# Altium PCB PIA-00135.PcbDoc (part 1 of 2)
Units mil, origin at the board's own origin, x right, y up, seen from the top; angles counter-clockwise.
Board outline 5630 x 2198.54 mil, 6 copper layers (Top Layer, Mid-Layer 1, Mid-Layer 2, Mid-Layer 3, Mid-Layer 4, Bottom Layer), stack 61.94 mil thick; 90 components, 35 nets, 210 pads, 457 vias.
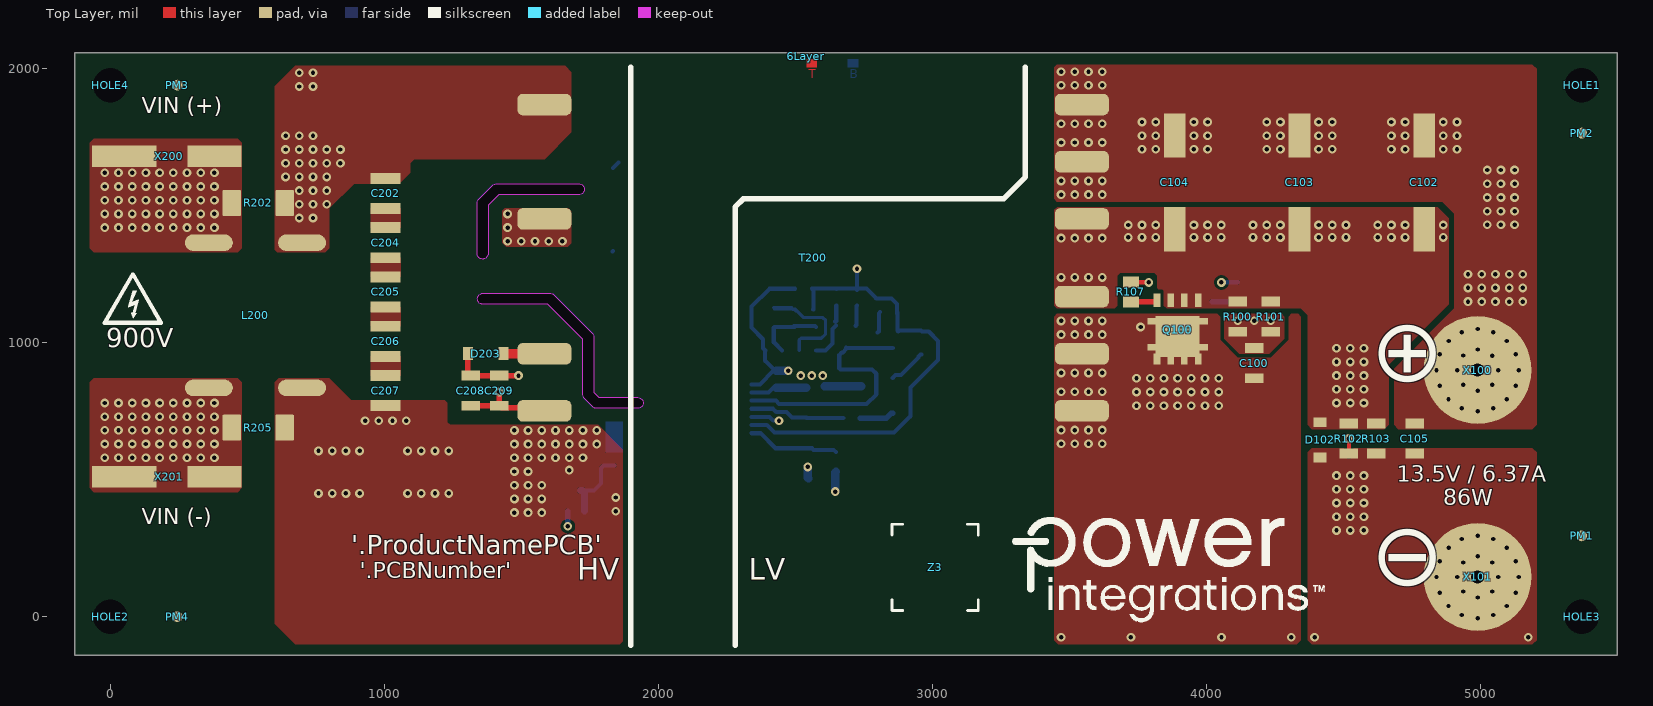
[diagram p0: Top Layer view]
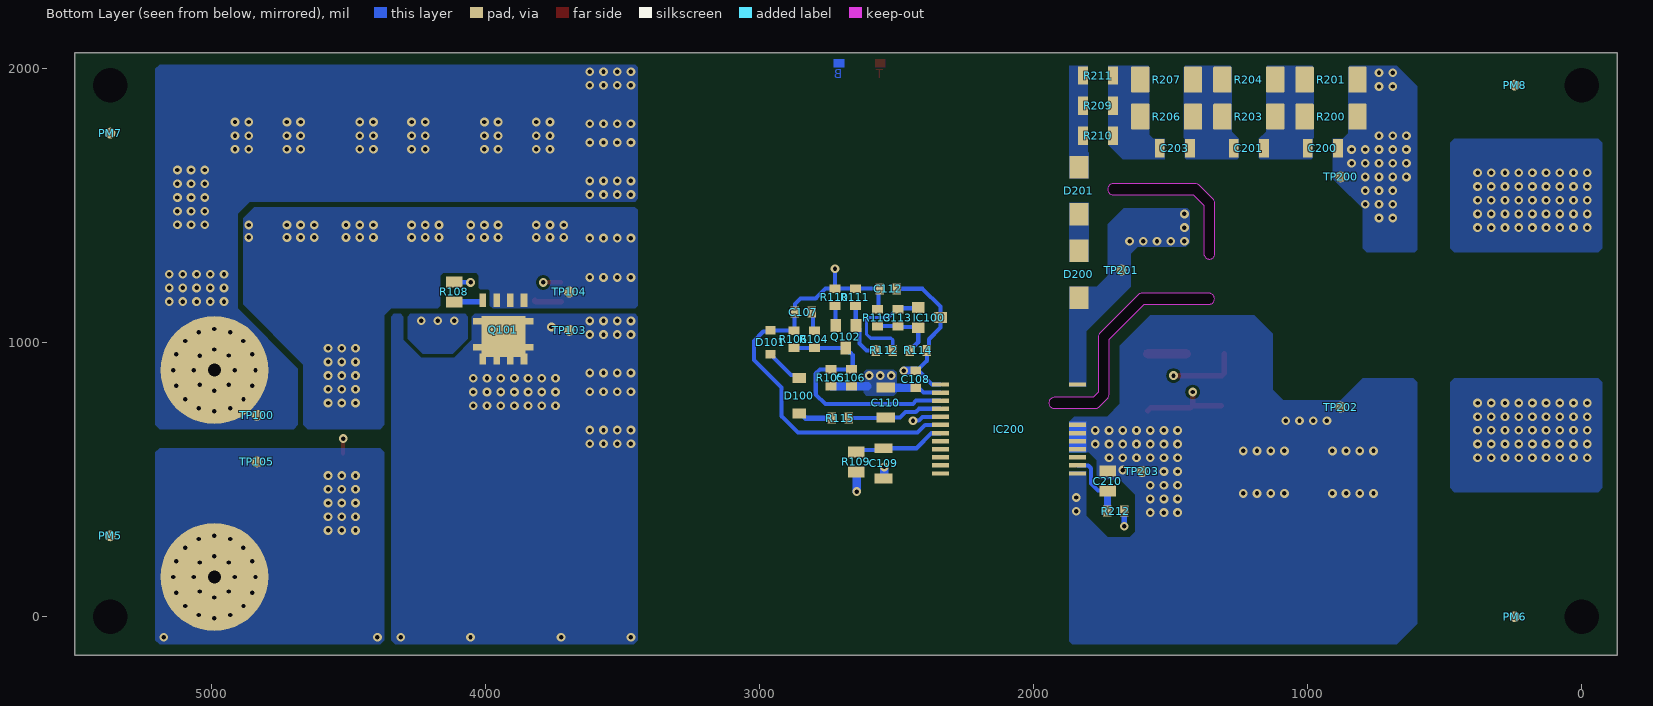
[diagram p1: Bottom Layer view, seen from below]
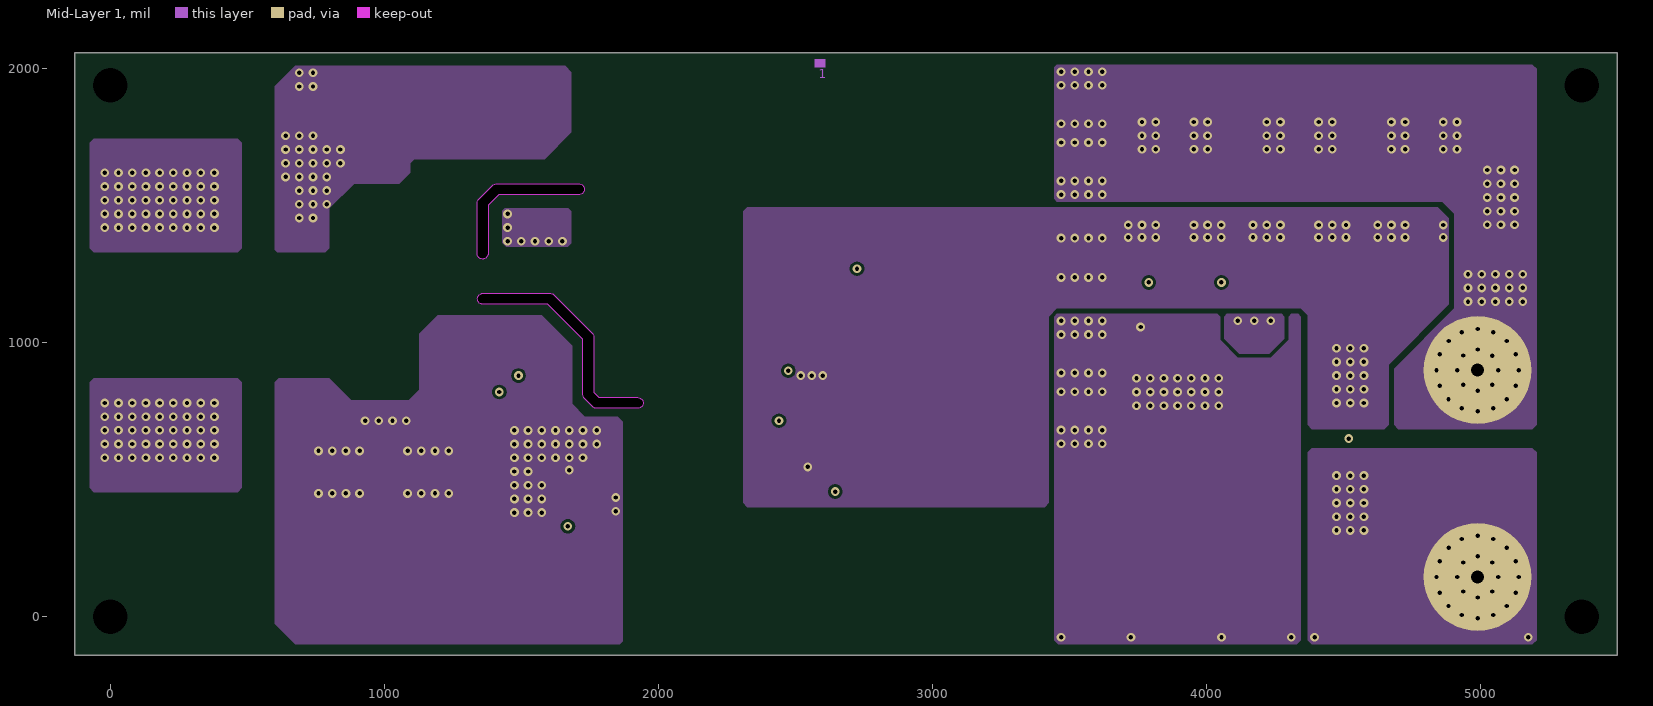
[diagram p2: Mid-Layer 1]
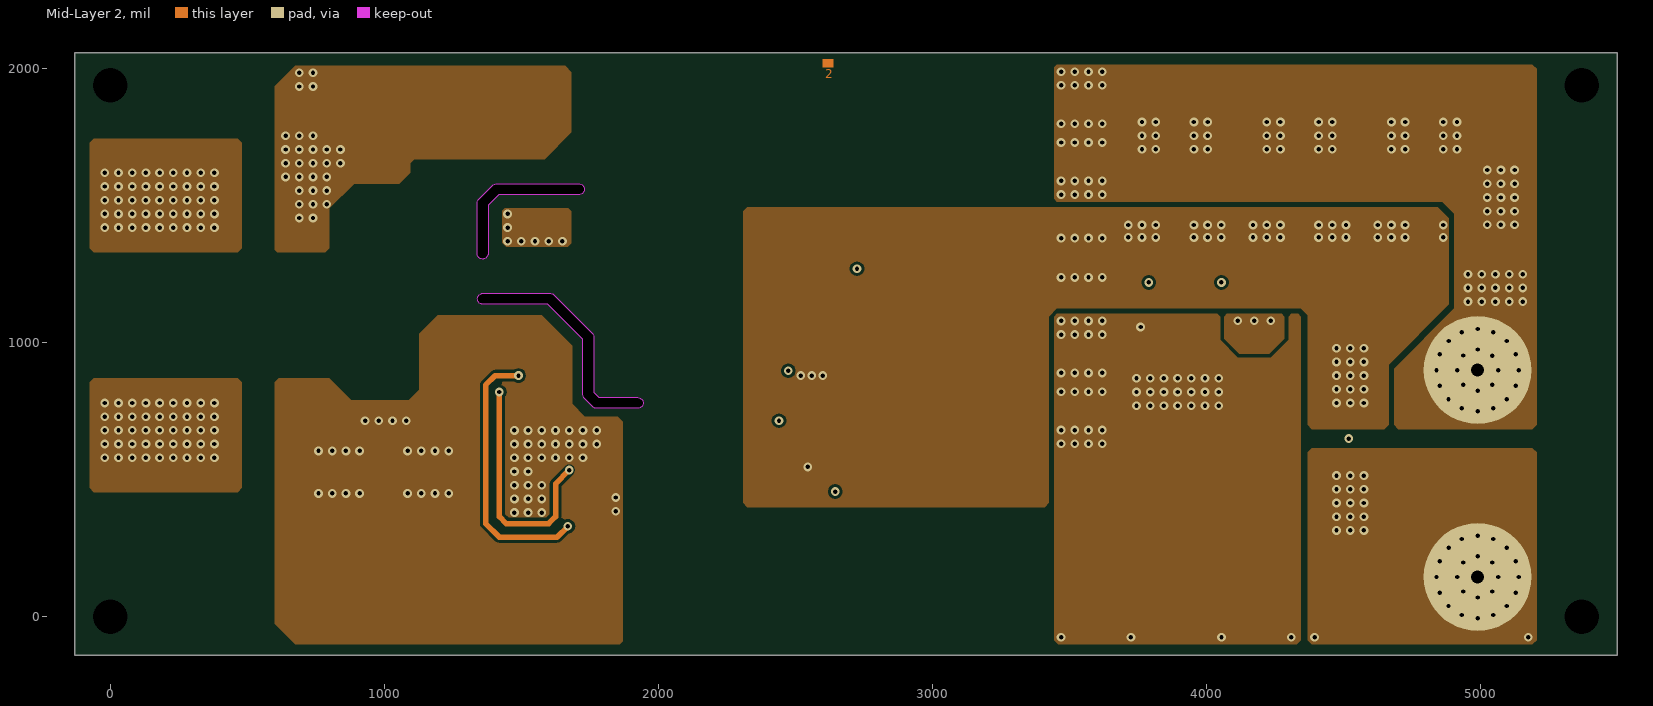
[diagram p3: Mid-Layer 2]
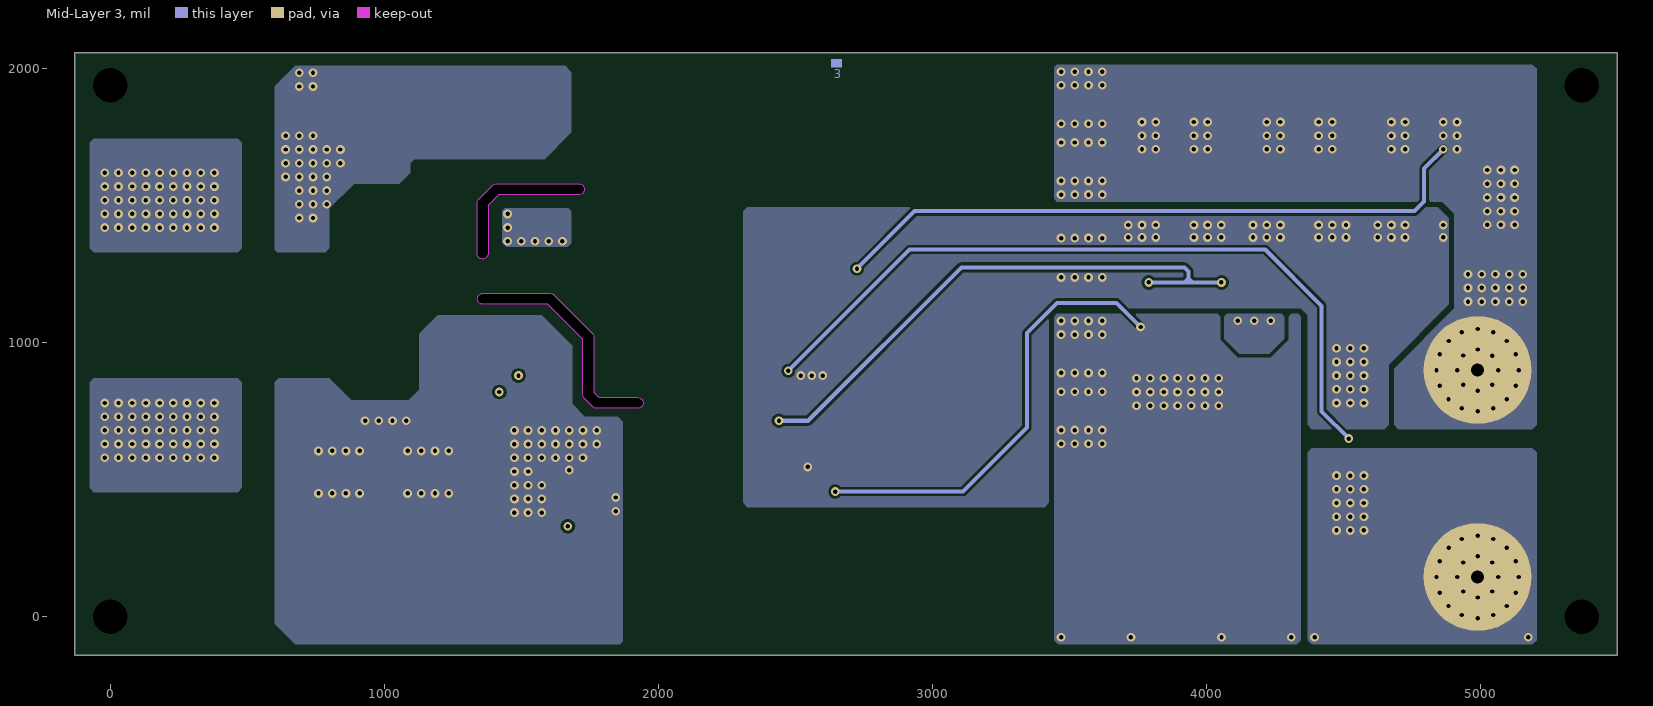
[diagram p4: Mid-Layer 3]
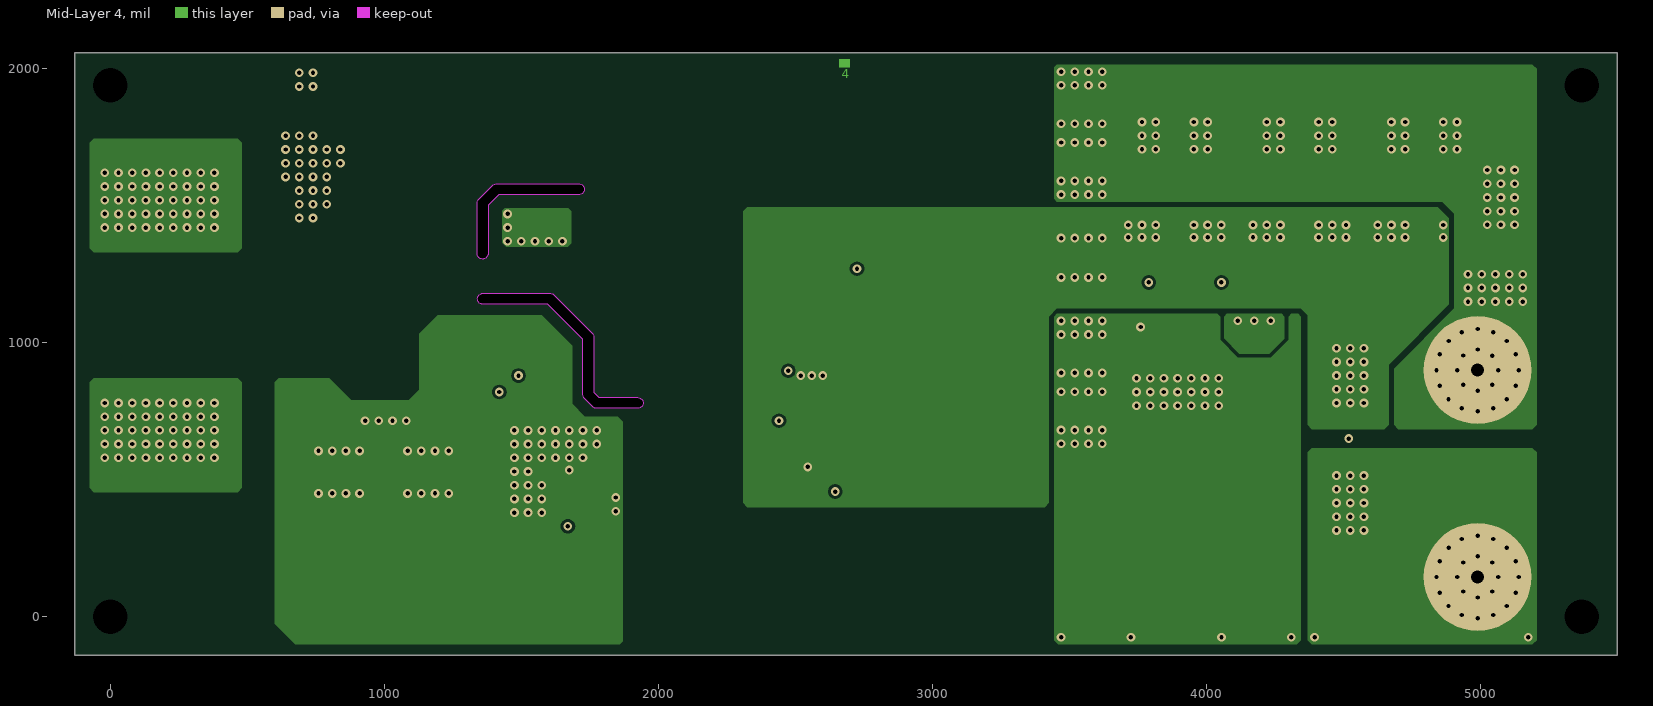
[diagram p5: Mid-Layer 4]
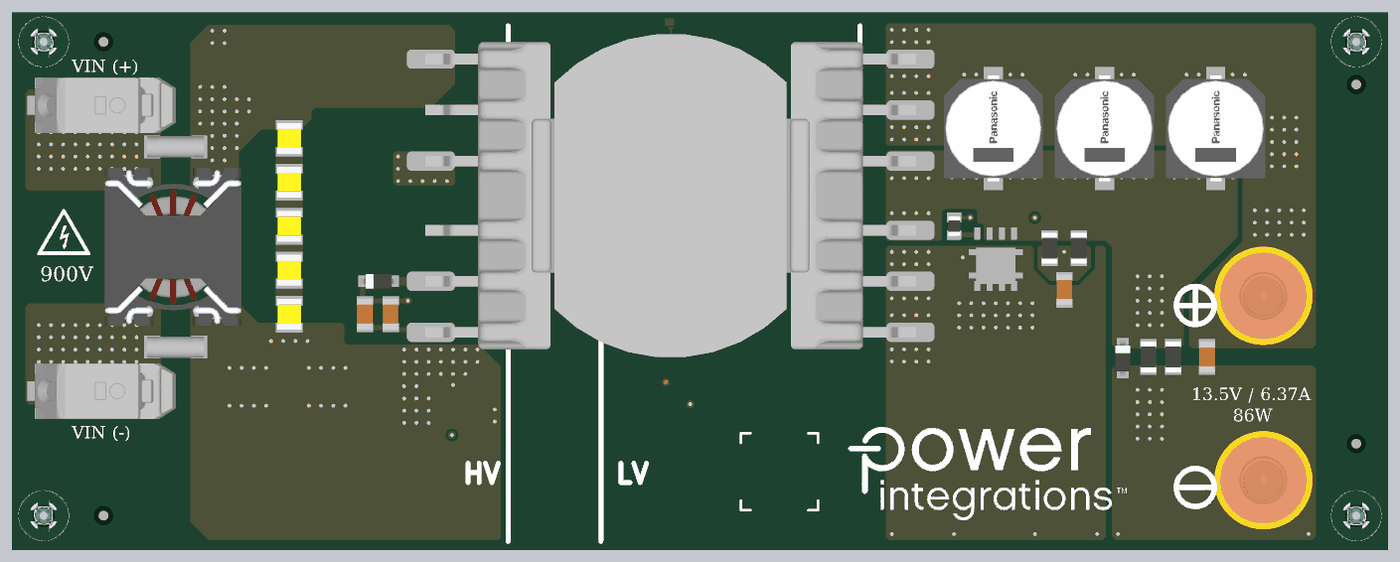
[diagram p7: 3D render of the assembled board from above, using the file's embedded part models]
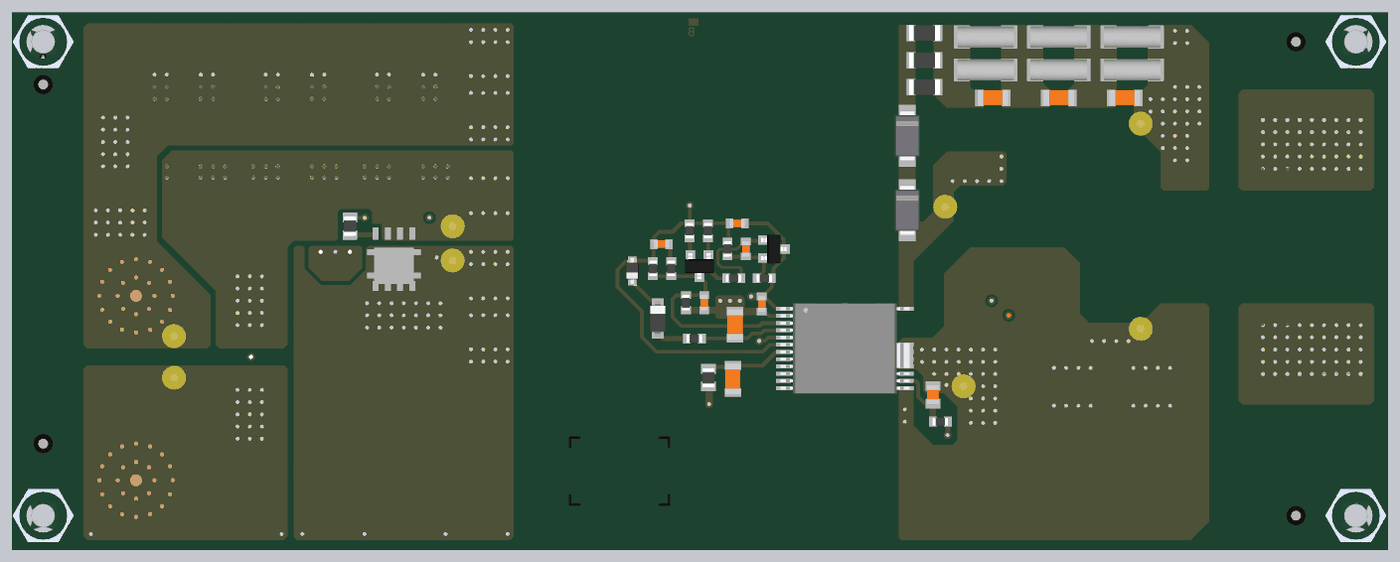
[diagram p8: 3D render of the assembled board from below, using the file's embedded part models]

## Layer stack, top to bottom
Top Solder: solder mask 0.39, Solder Resist, Dk 3.5
Top Layer: signal copper 1.4
Dielectric 8: prepreg 4.72, PP-1080, Dk 3.9
Mid-Layer 1: signal copper 1.4
Dielectric 14: core 19.69, Core, Dk 4.5
Mid-Layer 2: signal copper 1.4
Dielectric 9: prepreg 4.72, PP-2116, Dk 4.1
Mid-Layer 3: signal copper 1.4
Dielectric 13: core 19.69, Core, Dk 4.5
Mid-Layer 4: signal copper 1.4
Dielectric 11: prepreg 4.72, PP-1080, Dk 4.1
Bottom Layer: signal copper 1.4
Bottom Solder: solder mask 0.39, Solder Resist, Dk 3.5

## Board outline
-130,-140 -130,2058.54 5500,2058.54 5500,-140
cut-out: 1338.94,1325 1338.94,1508.96 cw(c1358.96,1508.96) 1344.84,1523.14 1344.8,1523.11 1395.84,1574.15 1395.81,1574.11 cw(c1410,1560) 1410,1580.01 1710,1580.01 cw(c1710,1560) 1730.01,1560 cw(c1710,1560) 1710,1539.98 1418.29,1539.98 1378.97,1500.67 1378.97,1325 cw(c1358.96,1325)
cut-out: 1724.98,810 1724.98,1011.71 1596.71,1139.98 1360,1139.98 cw(c1360,1160) 1360,1180.01 1605,1180.01 cw(c1605,1160) 1619.18,1174.11 1619.15,1174.15 1759.15,1034.15 1759.11,1034.18 cw(c1745,1020) 1765.01,1020 1765.01,818.29 1783.29,800.01 1925,800.01 cw(c1925,780) 1945.01,780 cw(c1925,780) 1925,759.98 1775,759.98 cw(c1775,780) 1760.81,765.88 1760.84,765.84 1730.84,795.84 1730.88,795.81 cw(c1745,810)

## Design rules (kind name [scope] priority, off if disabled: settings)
AcuteAngle [All] p1: minimum=8.90000000000000E+0001 checktracksonly=FALSE
Clearance "Clearance_X100 wrt via" [HasFootprint('ATV_CON_7466105R')] p1: gap=8 ignorepadtopadclearanceinfootprint=TRUE except(0: Arc-Hole Track-Hole SMDPad-Via SMDPad-Hole THPad-Hole Via-Hole Fill-Hole Poly-Hole Region-Hole Text-Hole)
Clearance "Clearance_Vbus1 wrt HV RTN" [InNet('VBus1') vs InNet('HV RTN')] p2: gap=3.94 ignorepadtopadclearanceinfootprint=FALSE
Clearance "Clearance_Vbus2 wrt HV RTN" [InNet('VBus2') vs InNet('HV RTN')] p3: gap=3.94 ignorepadtopadclearanceinfootprint=FALSE
Clearance "Clearance_Vbus3 wrt HV RTN" [InNet('VBus3') vs InNet('HV RTN')] p4: gap=3.94 ignorepadtopadclearanceinfootprint=FALSE
Clearance "Clearance_Vbus4 wrt HV RTN" [InNet('VBus4') vs InNet('HV RTN')] p5: gap=7.87 ignorepadtopadclearanceinfootprint=FALSE
Clearance "Clearance_Vsnub1 wrt HV RTN" [InNet('VSNUB1') vs InNet('HV RTN')] p6: gap=19.68 ignorepadtopadclearanceinfootprint=FALSE
Clearance "Clearance_Vsnub2 wrt HV RTN" [InNet('VSNUB2') vs InNet('HV RTN')] p7: gap=27.56 ignorepadtopadclearanceinfootprint=FALSE
Clearance "Clearance_Vsnub3 wrt HV RTN" [InNet('VSNUB3') vs InNet('HV RTN')] p8: gap=39.37 ignorepadtopadclearanceinfootprint=FALSE
Clearance "Clearance_Vsnub4 wrt HV RTN" [InNet('VSNUB4') vs InNet('HV RTN')] p9: gap=47.24 ignorepadtopadclearanceinfootprint=FALSE
Clearance "Clearance_Vsnub5 wrt HV RTN" [InNet('VSNUB5') vs InNet('HV RTN')] p10: gap=47.24 ignorepadtopadclearanceinfootprint=FALSE
Clearance "Clearance_Vsnub5 wrt Vsnub4" [InNet('VSNUB5') vs InNet('VSNUB4')] p11: gap=7.87 ignorepadtopadclearanceinfootprint=FALSE
Clearance "Clearance_HV+ wrt HV RTN" [InNet('HV+ (900 V)') vs InNet('HV RTN')] p12: gap=94.49 ignorepadtopadclearanceinfootprint=FALSE
Clearance "Clearance_HV+ wrt Vsnub1" [InNet('HV+ (900 V)') vs InNet('VSNUB1')] p13: gap=3.94 ignorepadtopadclearanceinfootprint=FALSE
Clearance "Clearance_HV+ wrt Vbus1" [InNet('HV+ (900 V)') vs InNet('VBus1')] p14: gap=7.87 ignorepadtopadclearanceinfootprint=FALSE
Clearance "Clearance_HV+ wrt Vbus2" [InNet('HV+ (900 V)') vs InNet('VBus2')] p15: gap=3.94 ignorepadtopadclearanceinfootprint=FALSE
Clearance "Clearance_HV+ wrt Vbus3" [InNet('HV+ (900 V)') vs InNet('VBus3')] p16: gap=3.94 ignorepadtopadclearanceinfootprint=FALSE
Clearance "Clearance_HV+ wrt Vbus4" [InNet('HV+ (900 V)') vs InNet('VBus4')] p17: gap=3.94 ignorepadtopadclearanceinfootprint=FALSE
Clearance "Clearance_HV+ wrt Vsnub2" [InNet('HV+ (900 V)') vs InNet('VSNUB2')] p18: gap=3.94 ignorepadtopadclearanceinfootprint=FALSE
Clearance "Clearance_HV+ wrt Vsnub3" [InNet('HV+ (900 V)') vs InNet('VSNUB3')] p19: gap=3.94 ignorepadtopadclearanceinfootprint=FALSE
Clearance "Clearance_HV+ wrt Vsnub4" [InNet('HV+ (900 V)') vs InNet('VSNUB4')] p20: gap=3.94 ignorepadtopadclearanceinfootprint=FALSE
Clearance "Clearance_HV+ wrt Vsnub5" [InNet('HV+ (900 V)') vs InNet('VSNUB5')] p21: gap=3.94 ignorepadtopadclearanceinfootprint=FALSE
Clearance "Clearance_HV+ wrt IC200_D" [InNet('HV+ (900 V)') vs InNet('IC200A_D')] p22: gap=15.75 ignorepadtopadclearanceinfootprint=FALSE
Clearance "Clearance_IC200A_D wrt HV RTN" [InNet('IC200A_D') vs InNet('HV RTN')] p23: gap=47.24 ignorepadtopadclearanceinfootprint=FALSE
Clearance "Clearance_IC200A_D wrt Vsnub5" [InNet('IC200A_D') vs InNet('VSNUB5')] p24: gap=27.56 ignorepadtopadclearanceinfootprint=FALSE
Clearance Clearance_Polygon [InPolygon] p25: gap=10 ignorepadtopadclearanceinfootprint=TRUE
Clearance "Clearance_PAD wrt outline" [HasPad('Free-x1')or HasPad('Free-x2')or HasPad('Free-x3')or HasPad('Free-x4')or HasPad('Free-x5')or HasPad('Free-x6')or HasPad('Free-x7')] p26: gap=0 ignorepadtopadclearanceinfootprint=TRUE
Clearance Clearance_TP [InComponent('TP*') vs InComponent('TP*')] p27: gap=40 ignorepadtopadclearanceinfootprint=TRUE except(0: Arc-Hole Track-Hole SMDPad-Hole THPad-Hole Via-Hole Fill-Hole Poly-Hole Region-Hole Text-Hole; 60: SMDPad-SMDPad)
Clearance "Clearance_minimum trace distance" [InNetClass('All Nets') vs InNetClass('All Nets')] p28: gap=7.99 ignorepadtopadclearanceinfootprint=TRUE
Clearance "Clearance_ pad 2 pad" [All] p29: gap=30 ignorepadtopadclearanceinfootprint=TRUE except(0: Arc-Arc Arc-Track Arc-SMDPad Arc-THPad Arc-Via Arc-Fill Arc-Poly Arc-Region Arc-Text Arc-Hole Track-Track Track-SMDPad Track-THPad Track-Via Track-Fill Track-Poly Track-Region Track-Text Track-Hole SMDPad-Fill SMDPad-Poly SMDPad-Region)
Clearance Clearance_Domains_Pri-Sec [InNetClass('Primary Side') vs (InNetClass('Secondary Side 1') OR InNetClass('Secondary Side 2'))] p30: gap=188.98 ignorepadtopadclearanceinfootprint=TRUE
Clearance Clearance_Domains_Sec-Sec [InNetClass('Secondary Side 1') vs InNetClass('Secondary Side 2')] p31: gap=255.91 ignorepadtopadclearanceinfootprint=TRUE except(0: Arc-Hole Track-Hole SMDPad-Hole THPad-Hole Via-Hole Fill-Hole Poly-Hole Region-Hole Text-Hole)
Clearance Clearance_VIA-PAD [IsVia vs IsPad AND NOT InComponent ('PM*')] p32: gap=1 ignorepadtopadclearanceinfootprint=TRUE except(0: Arc-Hole Track-Hole SMDPad-Hole THPad-Hole Via-Hole Fill-Hole Poly-Hole Region-Hole Text-Hole)
Clearance Clearance_Layer-Set [InComponent('*Layer')] p33: gap=10 ignorepadtopadclearanceinfootprint=TRUE except(30: SMDPad-SMDPad SMDPad-THPad THPad-THPad) // whole Board
Clearance Clearance_All [All] p34: gap=8 ignorepadtopadclearanceinfootprint=TRUE except(0: Arc-Hole Track-Hole SMDPad-Hole THPad-Hole Via-Hole Fill-Hole Poly-Hole Region-Hole Text-Hole; 30: SMDPad-SMDPad SMDPad-THPad THPad-THPad) // whole Board
ComponentClearance [All] p1: gap=40 collisioncheckmode=3 verticalgap=10 showdistances=FALSE donotcheckwithout3dbody=TRUE
Creepage "Creepage HV RTN wrt Vbus1" [InNet('HV RTN') vs InNet('VBus1')] p1: checkdistance=69.45 ignoreinternallayers=FALSE
Creepage "Creepage HV RTN wrt Vbus2" [InNet('HV RTN') vs InNet('VBus2')] p2: checkdistance=70.87 ignoreinternallayers=FALSE
Creepage "Creepage HV RTN wrt Vbus3" [InNet('HV RTN') vs InNet('VBus3')] p3: checkdistance=106.3 ignoreinternallayers=FALSE
Creepage "Creepage HV RTN wrt Vbus4" [InNet('HV RTN') vs InNet('VBus4')] p4: checkdistance=141.73 ignoreinternallayers=FALSE
Creepage "Creepage HV RTN wrt HV+" [InNet('HV RTN') vs InNet('HV+ (900 V)')] p5: checkdistance=177.17 ignoreinternallayers=FALSE
Creepage "Creepage HV RTN wrt BIAS Winding" [InNet('HV RTN') vs InNet('BIAS Winding')] p6: checkdistance=19.68 ignoreinternallayers=FALSE
Creepage "Creepage GND wrt SR-K" [InNet('13.5 V (RTN)') vs InNet('SR-K')] p7: checkdistance=23.62 ignoreinternallayers=FALSE
Creepage "Creepage GND wrt Vout" [InNet('13.5 V (RTN)') vs InNet('13.5 V (+)')] p8: checkdistance=19.68 ignoreinternallayers=FALSE
Creepage "Creepage HV RTN wrt BIAS_1" [InNet('HV RTN') vs InNet('BIAS')] p9: checkdistance=19.68 ignoreinternallayers=FALSE
Creepage "Creepage HV RTN wrt Vsnub1" [InNet('HV RTN') vs InNet('VSNUB1')] p10: checkdistance=157.48 ignoreinternallayers=FALSE
Creepage "Creepage HV RTN wrt Vsnub2" [InNet('HV RTN') vs InNet('VSNUB2')] p11: checkdistance=208.66 ignoreinternallayers=FALSE
Creepage "Creepage HV RTN wrt Vsnub3" [InNet('HV RTN') vs InNet('VSNUB3')] p12: checkdistance=267.72 ignoreinternallayers=FALSE
Creepage "Creepage HV RTN wrt Vsnub4" [InNet('HV RTN') vs InNet('VSNUB4')] p13: checkdistance=267.72 ignoreinternallayers=FALSE
Creepage "Creepage HV RTN wrt Vsnub5" [InNet('HV RTN') vs InNet('VSNUB5')] p14: checkdistance=224.41 ignoreinternallayers=FALSE
Creepage "Creepage HV RTN wrt IC200_D" [InNet('HV RTN') vs InNet('IC200A_D')] p15: checkdistance=192.91 ignoreinternallayers=FALSE
Creepage "Creepage Vsnub5 wrt Vsnub4" [InNet('VSNUB5') vs InNet('VSNUB4')] p16: checkdistance=59.06 ignoreinternallayers=FALSE
Creepage "Creepage HV+ wrt Vbus1" [InNet('HV+ (900 V)') vs InNet('VBus1')] p17: checkdistance=141.73 ignoreinternallayers=FALSE
Creepage "Creepage HV+ wrt Vbus2" [InNet('HV+ (900 V)') vs InNet('VBus2')] p18: checkdistance=106.3 ignoreinternallayers=FALSE
Creepage "Creepage HV+ wrt Vbus4" [InNet('HV+ (900 V)') vs InNet('VBus4')] p19: checkdistance=69.45 ignoreinternallayers=FALSE
Creepage "Creepage HV+ wrt Vbus3" [InNet('HV+ (900 V)') vs InNet('VBus3')] p20: checkdistance=70.87 ignoreinternallayers=FALSE
Creepage "Creepage HV+ wrt Vsnub1" [InNet('HV+ (900 V)') vs InNet('VSNUB1')] p21: checkdistance=62.99 ignoreinternallayers=FALSE
Creepage "Creepage HV+ wrt Vsnub2" [InNet('HV+ (900 V)') vs InNet('VSNUB2')] p22: checkdistance=55.12 ignoreinternallayers=FALSE
Creepage "Creepage HV+ wrt Vsnub3" [InNet('HV+ (900 V)') vs InNet('VSNUB3')] p23: checkdistance=86.61 ignoreinternallayers=FALSE
Creepage "Creepage HV+ wrt Vsnub4" [InNet('HV+ (900 V)') vs InNet('VSNUB4')] p24: checkdistance=86.61 ignoreinternallayers=FALSE
Creepage "Creepage HV+ wrt Vsnub5" [InNet('HV+ (900 V)') vs InNet('VSNUB5')] p25: checkdistance=55.12 ignoreinternallayers=FALSE
Creepage "Creepage HV+ wrt IC200_D" [InNet('HV+ (900 V)') vs InNet('IC200A_D')] p26: checkdistance=267.72 ignoreinternallayers=FALSE
Creepage "Creepage Vsnub1 wrt IC200_D" [InNet('Vsnub1') vs InNet('IC200A_D')] p27: checkdistance=86.61 ignoreinternallayers=FALSE
Creepage "Creepage Vsnub2 wrt IC200_D" [InNet('Vsnub2') vs InNet('IC200A_D')] p28: checkdistance=98.43 ignoreinternallayers=FALSE
Creepage "Creepage Vsnub3 wrt IC200_D" [InNet('Vsnub3') vs InNet('IC200A_D')] p29: checkdistance=118.11 ignoreinternallayers=FALSE
Creepage "Creepage Vsnub4 wrt IC200_D" [InNet('Vsnub4') vs InNet('IC200A_D')] p30: checkdistance=118.11 ignoreinternallayers=FALSE
Creepage "Creepage Vsnub5 wrt IC200_D" [InNet('Vsnub5') vs InNet('IC200A_D')] p31: checkdistance=59.06 ignoreinternallayers=FALSE
Creepage "Creepage primary wrt secondary inner layers" [InNetClass('Primary Side') vs InNetClass('Secondary Side 1')] p32: checkdistance=251.97 ignoreinternallayers=FALSE
Creepage "Creepage HV+ wrt HV- inner layers" [InNet('HV+ (900 V)') vs InNet('HV RTN')] p33: checkdistance=125.98 ignoreinternallayers=FALSE
Creepage "Creepage_primaty wrt secondary" [InNetClass('Primary Side') vs InNetClass('Secondary Side 1')] p34: checkdistance=393.7 ignoreinternallayers=FALSE
Height [All] p1: minheight=0 maxheight=2000 prefheight=500
HoleSize [All] p1: absolutevalues=TRUE maxlimit=220 minlimit=15.98 maxpercent=80.000 minpercent=20.000
HoleToHoleClearance [All] p1: gap=10 allowstackedmicrovias=FALSE
MinimumAnnularRing [All] p1: minimumring=8
MinimumSolderMaskSliver [All] p1 off: minsoldermaskwidth=10
NetAntennae [All] p1 off: netantennaetolerance=0
PasteMaskExpansion PasteMaskExpansion_TP [InComponent('TP*')] p1: expansion=-100 // cover TP
PasteMaskExpansion PasteMaskExpansion_All [All] p2: expansion=0
PolygonConnect [All vs IsNamedPolygon('PGND solder')] p1: thpad.connectstyle=Relief thpad.reliefconductorwidth=10 thpad.reliefentries=4 thpad.polygonreliefangle="90 Angle" thpad.airgapwidth=10 smdpad.connectstyle=Direct smdpad.reliefconductorwidth=10 smdpad.reliefentries=4 smdpad.polygonreliefangle="90 Angle" smdpad.airgapwidth=10 via.connectstyle=Relief via.reliefconductorwidth=10 via.reliefentries=4 via.polygonreliefangle="90 Angle" via.airgapwidth=10
PolygonConnect PolygonConnect_All [All] p2: connectstyle=Direct reliefconductorwidth=10 reliefentries=4 polygonreliefangle="90 Angle" airgapwidth=10 // Full Connect
RoutingVias [All] p1: holewidth=16 width=32 viastyle="Through Hole" minholewidth=16 minwidth=32 maxholewidth=16 maxwidth=32
SilkToSilkClearance [All] p1: silktosilkclearance=5
SilkToSolderMaskClearance SilkscreenOverComponentPads [IsPad] p1: minsilkscreentomaskgap=10 clearancetoexposedcopper=TRUE
SolderMaskExpansion SolderMaskExpansion_PM [InComponent('PM*')] p1: expansion=19.68 istentingtop=FALSE // 1mm
SolderMaskExpansion SolderMaskExpansion_VIA [(IsVia)] p2: expansion=-8 istentingtop=FALSE // cove copper
SolderMaskExpansion SolderMaskExpansion_All [All] p3 off: expansion=0 istentingtop=FALSE
UnpouredPolygon [All] p1: allowunpoured=TRUE
Width [All] p1: maxlimit=100 minlimit=10 preferedwidth=15
20 further rules are at their usual default settings.

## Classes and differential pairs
net class "Primary Side": BIAS "BIAS Winding" "HV RTN" "HV+ (900 V)" IC200A_D NetC210_1 NetIC1_8 NetIC1_9 NetIC1_10 NetIC1_11 NetIC1_12 NetIC1_15 NetL200_2 NetL200_3 Vbus1 Vbus2 Vbus3 Vbus4 Vsnub1 Vsnub2 Vsnub3 Vsnub4 Vsnub5
net class "Secondary Side 1": "13.5 V (+)" "13.5 V (RTN)" NetC100_2 NetC102_2 NetC107_2 NetC109_1 NetC110_1 NetC113_1 NetC113_2 NetD100_A NetD100_K NetIC200_5 NetQ100_G NetQ101_G NetQ102_B NetQ102_E SR-K VFB

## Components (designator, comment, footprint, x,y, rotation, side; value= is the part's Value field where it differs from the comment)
6Layer "6-Layer" PCB_6-LAYER 2540,2045 r0 top
C100 "1000p" ATV_1206_C_RS 4175,925 r90 top
C102 "560u" ATV_CAP_EEH-ZU1E561P 4795,1585 r270 top
C103 "560u" ATV_CAP_EEH-ZU1E561P 4340,1585 r270 top
C104 "560u" ATV_CAP_EEH-ZU1E561P 3885,1585 r270 top
C105 "1u" ATV_1206_C_RS 4760,650 r270 top
C106 "330p" ATV_0603_C_RS 2665.5,871.69 r90 bottom
C107 "10n" ATV_0603_C_RS 2840.5,1111.69 r180 bottom
C108 "2200p" ATV_0603_C_RS 2430.5,866.69 r90 bottom
C109 "330p" ATV_1206_C_RS 2548.14,559.69 r270 bottom
C110 "2u2" ATV_1206_C_RS 2540.5,781.69 r90 bottom
C112 "N.A." ATV_0603_C_RS 2530.5,1196.69 r180 bottom
C113 "1u" ATV_0603_C_RS 2495.5,1091.69 r270 bottom
C200 "22n" ATV_1206_C_RS 945,1710 r0 bottom
C201 "22n" ATV_1206_C_RS 1215,1710 r0 bottom
C202 "" ATV_1210_C_RS 1005,1545 r270 top value=150n
C203 "22n" ATV_1206_C_RS 1485,1710 r0 bottom
C204 "150n" ATV_1210_C_RS 1005,1365 r270 top
C205 "150n" ATV_1210_C_RS 1005,1185 r270 top
C206 "150n" ATV_1210_C_RS 1005,1005 r270 top
C207 "150n" ATV_1210_C_RS 1005,825 r270 top
C208 "10u" ATV_1206_C_RS 1315,825 r270 top
C209 "10u" ATV_1206_C_RS 1420,825 r270 top
C210 "470n" ATV_0805_C_RS 1730,495 r90 bottom
D100 "PDZ15BGWX" ATV_SOD123_RS 2855.5,806.69 r270 bottom
D101 "BAS16J,115" ATV_SOD-323 2960.5,1001.69 r90 bottom
D102 "PMEG4030ER,115" ATV_SOD123_RS 4415,645 r270 top value=PMEG4030ER/8X
D200 "ACURA107" ATV_DIODE_SMA 1835,1250 r270 bottom
D201 "ACURA107" ATV_DIODE_SMA 1835,1555 r270 bottom
D203 "" ATV_SOD123_RS 1370,960 r0 top value=BAS21GWX
HOLE1 "HOLE-3.2mm" PCB_HOLE-3.2_with_standoff 5370,1940 r0 top
HOLE2 "HOLE-3.2mm" PCB_HOLE-3.2_with_standoff 0,0 r180 top
HOLE3 "HOLE-3.2mm" PCB_HOLE-3.2_with_standoff 5370,0 r0 top
HOLE4 "HOLE-3.2mm" PCB_HOLE-3.2_with_standoff 0,1940 r0 top
IC100 "ATL431LIBQDBZRQ1" CT_SOT23_RS 2380.5,1091.69 r270 bottom
IC200 "INN3949CQ" ATV_InSOP-24D 2090,685 r180 bottom
L200 "1.4mH" "CT_IND_CMC_FT-3K70T F1613Y_RS" 529.92,1100.04 r270 top
PM1 "FIDUCIAL" PCB_FIDUCIAL 5370,295 r0 top
PM2 "FIDUCIAL" PCB_FIDUCIAL 5370,1765 r0 top
PM3 "FIDUCIAL" PCB_FIDUCIAL 245,1940 r0 top
PM4 "FIDUCIAL" PCB_FIDUCIAL 245,0 r180 top
PM5 "FIDUCIAL" PCB_FIDUCIAL 5370,295 r180 bottom
PM6 "FIDUCIAL" PCB_FIDUCIAL 245,0 r0 bottom
PM7 "FIDUCIAL" PCB_FIDUCIAL 5370,1765 r180 bottom
PM8 "FIDUCIAL" PCB_FIDUCIAL 245,1940 r180 bottom
Q100 "DMT12H007LPS-13" CT_PowerDI5060-8_RS 3895,1050 r180 top
Q101 "DMT12H007LPS-13" ATV_PowerDI5060-8_RS 3935,1050 r0 bottom
Q102 "MMBT3906-7-F" CT_SOT23_RS_BIP 2685.5,1021.69 r0 bottom
R100 "12R" ATV_1206_R_RS 4115,1095 r90 top
R101 "12R" ATV_1206_R_RS 4235,1095 r90 top
R102 "0R01" ATV_1206_R_RS 4520,650 r270 top
R103 "0R01" ATV_1206_R_RS 4620,650 r270 top
R104 "10k" ATV_0603_R_RS 2800.5,1011.69 r90 bottom
R105 "10k2" ATV_0603_R_RS 2740.5,871.69 r90 bottom
R106 "110k" ATV_0603_R_RS 2875.5,1011.69 r90 bottom
R107 "3R9" ATV_0805_R_RS 3725,1185 r90 top
R108 "3R9" ATV_0805_R_RS 4115,1185 r90 bottom
R109 "100R" ATV_0805_R_RS 2648.14,564.69 r90 bottom
R110 "470k" ATV_0603_R_RS 2725.5,1166.69 r270 bottom
R111 "33k" ATV_0603_R_RS 2650.5,1166.69 r270 bottom
R112 "11k" ATV_0603_R_RS 2545.5,971.69 r180 bottom
R113 "110k" ATV_0603_R_RS 2570.5,1091.69 r270 bottom
R114 "24k9" ATV_0603_R_RS 2420.5,971.69 r180 bottom
R115 "100R" ATV_0603_R_RS 2706,725 r0 bottom
R200 "150k" ATV_MELF_0207 915,1825 r0 bottom
R201 "150k" ATV_MELF_0207 915,1960 r0 bottom
R202 "N.A." ATV_MELF_0207 540,1510 r0 top
R203 "150k" ATV_MELF_0207 1215,1825 r0 bottom
R204 "150k" ATV_MELF_0207 1215,1960 r0 bottom
R205 "N.A." ATV_MELF_0207 540,690 r0 top
R206 "150k" ATV_MELF_0207 1515,1825 r0 bottom
R207 "150k" ATV_MELF_0207 1515,1960 r0 bottom
R209 "43R" ATV_1206_R_RS 1765,1865 r0 bottom
R210 "43R" ATV_1206_R_RS 1765,1755 r0 bottom
R211 "43R" ATV_1206_R_RS 1765,1975 r0 bottom
R212 "4k7" ATV_0603_R_RS 1700,385 r0 bottom
T200 "TRF_POT3319" ATV_TRF_POT3319 2565,1310 r0 top value=POT3319
TP100 "ICT-100SP-BL" ICT-100SP-BL-40MIL 4835,735 r90 top
TP103 "ICT-100SP-BL" ICT-100SP-BL-40MIL 3695,1045 r90 top
TP104 "ICT-100SP-BL" ICT-100SP-BL-40MIL 3695,1185 r90 top
TP105 "ICT-100SP-BL" ICT-100SP-BL-40MIL 4835,565 r90 top
TP200 "ICT-100SP-BL" ICT-100SP-BL-40MIL 880,1605 r90 top
TP201 "ICT-100SP-BL" ICT-100SP-BL-40MIL 1680,1265 r90 top
TP202 "ICT-100SP-BL" ICT-100SP-BL-40MIL 880,765 r90 top
TP203 "ICT-100SP-BL" ICT-100SP-BL-40MIL 1605,530 r90 top
X100 "7466105R" ATV_CON_7466105R 4990,900 r0 top
X101 "7466105R" ATV_CON_7466105R 4990,145 r0 top
X200 "SM99S01VBNN04G7" ATV_METZ_SM99S01VB 360,1680 r180 top
X201 "SM99S01VBNN00G7" ATV_METZ_SM99S01VB 360,510 r180 top
Z3 "Traceability Label 2" ATV_TRACEABILITY_LABEL2 3010,180 r0 top

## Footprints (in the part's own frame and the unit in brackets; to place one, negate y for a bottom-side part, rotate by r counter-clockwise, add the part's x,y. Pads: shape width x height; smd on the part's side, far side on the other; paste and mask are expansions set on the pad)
ATV_0603_C_RS [mil]
  rect 31x40 smd: 1(-31,0) 2(31,0)
  body extent -32,-16 31,15, height 20
ATV_0603_R_RS [mil]
  rect 31x40 smd: 1(-31,0) 2(31,0)
  body extent -31,-16 31,16, height 18
ATV_0805_C_RS [mil]
  rect 40x60 smd: 1(-36,0) 2(36,0)
  body extent -39,-24 39,25, height 24
ATV_0805_R_RS [mil]
  rect 40x60 smd: 1(-36,0) 2(36,0)
  body extent -39,-25 39,25, height 24
ATV_1206_C_RS [mil]
  rect 36x67 smd: 1(-55,0) 2(55,0)
  body extent -63,-32 63,31, height 31
ATV_1206_R_RS [mil]
  rect 36x67 smd: 1(-55,0) 2(55,0)
  body extent -63,-31 63,32, height 24
ATV_1210_C_RS [mil]
  rect 40x110 smd: 1(-55,0) 2(55,0)
  body extent -63,-49 63,49, height 98
ATV_CAP_EEH-ZU1E561P [mm]
  rect 4.1x2 smd paste+0 mask+0: 1(-4.35,0) 2(4.35,0)
  body extent -5.5,-5.15 5.5,5.15, height 16.8
ATV_CON_7466105R [mm]
  round 10 hole 1.2 mask+0.102: 1(0,0)
  body extent -4.5,-4.5 4.5,4.5, height 7.1
ATV_DIODE_SMA [mil]
  rect 82x70 smd: A(86,0) K(-86,0)
  body extent -102,-51 102,51, height 95
ATV_InSOP-24D [mm]
  rect 1.58x0.41 smd paste+0 mask+0: 1(-6.363,4.125) 2(-6.363,3.375) 3(-6.363,2.625) 4(-6.363,1.875) 5(-6.363,1.125) 6(-6.363,0.375) 7(-6.363,-0.375) 8(-6.363,-1.125) 9(-6.363,-1.875) 10(-6.363,-2.625) 11(-6.363,-3.375) 12(-6.363,-4.125) 13(6.363,-4.125) 14(6.363,-3.375) 15(6.363,-2.625) 16-19(6.363,-1.875) 16-19(6.363,-1.125) 16-19(6.363,-0.375) 16-19(6.363,0.375) 24(6.363,4.125)
  Top Layer region: 5.575,-2.159 5.575,0.66 7.15,0.66 7.15,-2.159
  body extent -6.72,-4.7 6.72,4.7, height 1.7
ATV_MELF_0207 [mm]
  rrect10% 1.7x2.4 smd: 1(-2.45,0) 2(2.45,0)
  body extent -2.95,-1.11 2.95,1.11, height 2.23
ATV_METZ_SM99S01VB [mm]
  rect 5x2 smd: 1(-0.5,0)
  rect 6x2 smd: 2(7.85,0)
  body extent -4.6,-2.9 10.08,2.9, height 6.7
ATV_PowerDI5060-8_RS [mm]
  rect 0.61x1.02 smd: D(-1.905,2.795) D(-0.635,2.795) D(0.635,2.795) D(1.905,2.795)
  rect 5.61x0.6 smd: D(0,-0.735) D(0,1.69)
  rect 4.1x3.81 smd: D(0,0.69)
  rect 0.61x1.27 smd: G(1.905,-2.67) S(-1.905,-2.67) S(-0.635,-2.67) S(0.635,-2.67)
  body extent -2.57,-3.07 2.57,3.07, height 1.1
ATV_SOD123_RS [mil]
  rect 36x48 smd: A(64.61,0) K(-64.61,0)
  body extent -73,-32 73,31, height 50
ATV_SOD-323 [mm]
  rect 0.8x0.9 smd mask+0.051: A(1.1,0) K(-1.1,0)
  body extent -1.35,-0.67 1.35,0.67, height 0.79
ATV_TRACEABILITY_LABEL2 [mil]
  silkscreen extent -157,-157 157,157, body extent -157,-157 157,157, height 10
ATV_TRF_POT3319 [mm]
  rrect50% 5x2 smd: 1(-24.91,14.2) 3(-24.91,3.6) 5(-24.91,-8.9) 6(-24.91,-14.2) 7(24.91,-14.2) 8(24.91,-8.9) 9(24.91,-3.6) 10(24.91,3.6) 11(24.91,8.9) 12(24.91,14.2)
  body extent -25.5,-16.85 25.5,16.85, height 21.7
"CT_IND_CMC_FT-3K70T F1613Y_RS" [mm]
  oval 1.52x4.45 smd: 1(-6.73,4.32) 2(-6.73,-4.32) 3(6.73,-4.32) 4(6.73,4.32)
  body extent -8.19,-7.11 8.19,7.11, height 8.89
CT_PowerDI5060-8_RS [mm]
  rect 0.61x1.02 smd: D(-1.905,2.795) D(-0.635,2.795) D(0.635,2.795) D(1.905,2.795)
  rect 5.61x0.6 smd: D(0,1.69) D(0,-0.735)
  rect 4.1x3.81 smd: D(0,0.69)
  rect 0.61x1.27 smd: G(1.905,-2.67) S(-1.905,-2.67) S(-0.635,-2.67) S(0.635,-2.67)
  body extent -2.57,-3.07 2.57,3.07, height 1.1
CT_SOT23_RS [mil]
  rect 39x47 smd: 1(-37,-41) 2(37,-41) 3(0,41)
  body extent -59,-52 59,52, height 43
CT_SOT23_RS_BIP [mil]
  rect 39x47 smd: B(-37,-41) C(0,41) E(37,-41)
  body extent -59,-52 59,52, height 43
ICT-100SP-BL-40MIL [mil]
  round 40 smd far side paste-20: 1(0,0)
  round 40 on Mech16: 2(0,0)
  body extent -49,-49 49,49, height 579
PCB_6-LAYER [mil] "PCB-Layer-control"
  Top Layer region: 0,-10 0,-40 40,-40 40,-10
  Mid-Layer 1 region: 30,-10 30,-40 70,-40 70,-10
  Mid-Layer 4 region: 120,-10 120,-40 160,-40 160,-10
  Mid-Layer 2 region: 60,-10 60,-40 100,-40 100,-10
  Mid-Layer 3 region: 90,-10 90,-40 130,-40 130,-10
  Bottom Layer region: 150,-10 150,-40 190,-40 190,-10
PCB_FIDUCIAL [mm] "Fiducial rund ohne Anschluss"
  round 1 smd mask+0.5: 0(0,0)
PCB_HOLE-3.2_with_standoff [mm]
  round 0 hole 3.2 unplated: 0(0,0)
  body extent -3.18,-2.75 3.18,2.75, height 2

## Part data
6Layer: library part ATV-MISC-0011
C100: library part ATV-CAP-0396, Dielectric=NP0,C0G, Manufacturer 1="TDK Corporation", Package=1206, Temperature Range="-55 to +125°C", Tolerance=5%, Voltage=630V
C102 C103 C104: library part ATV-CAP-0337, Dielectric=AL, Manufacturer 1="Panasonic Electronic Components", Package=10.3X10.3mm, Temperature Range="-55 to +135°C", Tolerance=20%, Voltage=25V
C105: library part ATV-CAP-0418, Dielectric=X7R, Manufacturer 1="TDK Corporation", Package=1206, Temperature Range="-55 to +125°C", Tolerance=10%, Voltage=50V
C106: library part ATV-CAP-0354, Dielectric=C0G, Manufacturer 1="TDK Corporation", Package=0603, Temperature Range="-55 to +125°C", Tolerance=5%, Voltage=50V
C107: library part ATV-CAP-0263, Dielectric=X7R, Manufacturer 1=KEMET, Package=0603, Temperature Range="-55 to +125°C", Tolerance=10%, Voltage=50V
C108: library part ATV-CAP-0417, Dielectric=NP0,C0G, Manufacturer 1="Murata Electronics", Package=0603, Temperature Range="-55 to +125°C", Tolerance=5%, Voltage=50V
C109: library part ATV-CAP-0312, Dielectric=C0G, Manufacturer 1=KEMET, Package=1206, Temperature Range="-55 to +125°C", Tolerance=10%, Voltage=500V
C110: library part ATV-CAP-0355, Dielectric=X7R, Manufacturer 1="TDK Corporation", Package=1206, Temperature Range="-55 to +125°C", Tolerance=20%, Voltage=25V
C112: library part ATV-CAP-0296, Package=0603
C113: library part ATV-CAP-0358, Dielectric=X7R, Manufacturer 1="TDK Corporation", Package=0603, Temperature Range="-55 to +125°C", Tolerance=20%, Voltage=25V
C200 C201 C203: library part ATV-CAP-0352, Dielectric=X7R, Manufacturer 1=Murata, Package=1206, Temperature Range="-55 to +125°C", Tolerance=10%, Voltage=250V
C202 C204 C205 C206 C207: library part ATV-CAP-0309, Dielectric=X7R, Manufacturer 1=KEMET, Package=1210, Temperature Range="-55 to +125°C", Tolerance=10%, Voltage=500V
C208 C209: library part ATV-CAP-0266, Dielectric=X7R, Manufacturer 1=TDK, Package=1206, Temperature Range="-55 to +125°C", Tolerance=10%, Voltage=50V
C210: library part ATV-CAP-0264, Dielectric=X7R, Manufacturer 1=YAGEO, Package=0805, Temperature Range="-55 to +125°C", Tolerance=10%, Voltage=16V
D100: library part ATV-DIO-0117, Current="50 nA @ 11 V", Forward Voltage="1.1 V @ 100 mA", Manufacturer 1="Nexperia USA Inc.", Package=SOD123, Power=365mW, Reverse Voltage=15V, Temperature Range="-55 to +150°C", Tolerance=2.13%
D101: library part ATV-DIO-0104, Current="500 nA @ 80 V", Forward Voltage="1.25 V @ 150 mA", Manufacturer 1=Nexperia, Package=SOD-323, Reverse Voltage=100V, Temperature Range="-55 to +150°C"
D102: library part ATV-DIO-0134, Current="100 µA @ 40 V", Forward Voltage="540 mV @ 3 A", Manufacturer 1="Nexperia USA Inc.", Package=SOD123W, Reverse Voltage=40V, Temperature Range="-55 to +150°C"
D200 D201: library part ATV-DIO-0072, Current=1A, Forward Voltage="1.7 V @ 1 A", Manufacturer 1="Comchip Technology", Package="DO-214AC (SMA)", Reverse Voltage=1000V, Temperature Range="-55 to +150°C"
D203: library part ATV-DIO-0036, Current=200mA, Forward Voltage="1.25v @ If {} 200mA", Manufacturer 1=Nexperia, Package=SOD-123, Power=250mW, Reverse Voltage=250V, Temperature Range="-65 to +150°C"
HOLE1 HOLE2 HOLE3 HOLE4: library part ATV-MISC-0013, Package="3.2mm Hole"
IC100: library part ATV-IC-0058, Manufacturer 1="Texas Instruments", Output Current=15mA, Package=SOT-23, Supply Voltage="2.5 V to 36 V", Temperature Range="-40 to +125°C"
IC200: library part ATV-IC-0054, Manufacturer 1="Power Integrations", Package=InSOP-24D, Supply Voltage="4.65V to 5.15V", Temperature Range="-40 to +150°C"
L200: library part ATV-IND-0016, Current=2.5A, Manufacturer 1=Coilcraft, Package=CM6518-AL, Resistor=60mOhm, Temperature Range="-40 to +125°C"
PM1 PM2 PM3 PM4 PM5 PM6 PM7 PM8: library part ATV-MISC-0007
Q100 Q101: library part ATV-FET-0039, Current=90A, Manufacturer 1=Diodes, Package=PowerDI5060-8, Power=2.9W, Resistor="7.8mOhm @ Vgs {} 10V / Id {} 30", Temperature Range="-55 to +150°C", Voltage=120V
Q102: library part ATV-BIP-0012, Current=0.2A, Manufacturer 1=Diodes, Package=SOT-23, Power=300mW, Temperature Range="-55 to +150°C", Voltage=40V
R100 R101: library part ATV-RES-0824, Manufacturer 1=YAGEO, Package=1206, Power=0.25W, Temperature Range="-55 to +155°C", Tolerance=5%
R102 R103: library part ATV-RES-1073, Manufacturer 1="Vishay Dale", Package=1206, Power=0.25W, Temperature Range="-65 to +170°C", Tolerance=0.5%, Voltage=200V
R104: library part ATV-RES-0827, Manufacturer 1=YAGEO, Package=0603, Power=0.1W, Temperature Range="-55 to +155°C", Tolerance=5%
R105: library part ATV-RES-0938, Manufacturer 1="Stackpole Electronics Inc", Package=0603, Power=0.1W, Temperature Range="-55 to +155°C", Tolerance=1%
R106: library part ATV-RES-0946, Manufacturer 1="Stackpole Electronics Inc", Package=0603, Power=0.1W, Temperature Range="-55 to +155°C", Tolerance=5%
R107 R108: library part ATV-RES-0936, Manufacturer 1="Stackpole Electronics Inc", Package=0805, Power=0.125W, Temperature Range="-55 to +155°C", Tolerance=5%
R109: library part ATV-RES-0939, Manufacturer 1="Stackpole Electronics Inc", Package=0805, Power=0.125W, Temperature Range="-55 to +155°C", Tolerance=5%
R110: library part ATV-RES-0944, Manufacturer 1="Stackpole Electronics Inc", Package=0603, Power=0.1W, Temperature Range="-55 to +155°C", Tolerance=5%
R111: library part ATV-RES-0945, Manufacturer 1="Stackpole Electronics Inc", Package=0603, Power=0.1W, Temperature Range="-55 to +155°C", Tolerance=5%
R112: library part ATV-RES-0947, Manufacturer 1="Stackpole Electronics Inc", Package=0603, Power=0.1W, Temperature Range="-55 to +155°C", Tolerance=5%
R113: library part ATV-RES-0943, Manufacturer 1="Stackpole Electronics Inc", Package=0603, Power=0.1W, Temperature Range="-55 to +155°C", Tolerance=1%
R114: library part ATV-RES-0942, Manufacturer 1="Stackpole Electronics Inc", Package=0603, Power=0.1W, Temperature Range="-55 to +155°C", Tolerance=1%
R115: library part ATV-RES-0753, Manufacturer 1="Stackpole Electronics Inc", Package=0603, Power=0.1W, Temperature Range="-55 to +155°C", Tolerance=5%
R200 R201 R203 R204 R206 R207: library part ATV-RES-0979, Manufacturer 1="Vishay / Beyschlag", Package="MELF 0207", Power=1W, Temperature Range="-55 to +155°C", Tolerance=2%, Voltage=200V
R202 R205: library part ATV-RES-1026, Package="MELF 0207", Power=1W, Temperature Range="-55 to +155°C", Tolerance=1%, Voltage=200V
R209 R210 R211: library part ATV-RES-0750, Manufacturer 1="Stackpole Electronics Inc", Package=1206, Power=0.25W, Temperature Range="-55 to +155°C", Tolerance=5%
R212: library part ATV-RES-0937, Manufacturer 1="Stackpole Electronics Inc", Package=0603, Power=0.1W, Temperature Range="-55 to +155°C", Tolerance=5%
T200: library part ATV-TRF-0031, Manufacturer 1="Power Integrations", Package=POT3319
TP100 TP103 TP104 TP105 TP200 TP201 TP202 TP203: library part ATV-MISC-0002, Manufacturer 1="UWE electronic", Package=N
X100 X101: library part ATV-CON-0090, Current=70A, Manufacturer 1="Würth Elektronik"
X200: library part ATV-MISC-0037, Manufacturer 1="METZ CONNECT USA Inc.", Temperature Range="-40 to +105°C"
X201: library part ATV-MISC-0036, Manufacturer 1="METZ CONNECT USA Inc.", Temperature Range="-40 to +105°C"
Z3: library part ATV-LABEL-0016, Manufacturer 1="power integrations"

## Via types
v1: diameter 32, hole 16, Top Layer to Bottom Layer, tented both sides, 409 vias
v2: diameter 32, hole 16, Top Layer to Bottom Layer, tented bottom, 48 vias

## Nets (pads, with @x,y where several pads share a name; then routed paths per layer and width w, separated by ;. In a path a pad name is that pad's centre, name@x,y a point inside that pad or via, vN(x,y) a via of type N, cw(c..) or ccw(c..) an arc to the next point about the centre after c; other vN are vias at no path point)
"13.5 V (+)": C102.1 C103.1 C104.1 C105.1 C107.1 C112.1 D101.A IC200.6 R106.2 R110.1 R111.1 R113.1 T200.11 T200.12 TP100.1 X100.1 | length 4087.8
  Mid-Layer 3 w15: v1(2725,1270) 2935,1480 4760,1480 4795,1515 4795,1635.95 v1(4864.6,1705.56)
  Bottom Layer w15: IC200.6@2340.5,699.76 2395.93,699.76 2424,671.69 2860.5,671.69 2920.5,731.69 2920.5,836.69 3020.5,936.69 3020.5,1006.69 2986.98,1040.21 2961.98,1040.21 2958.34,1043.84 2876.65,1043.84 R106.2@2875.5,1042.69 ; R113.1@2565.5,1121.69 2566,1122.19 2566,1192.19 C112.1@2561.5,1196.69 2562,1197.19 R111.1@2650.5,1197.19 ; R111.1@2650.5,1196.69 2651.5,1197.69 R110.1@2721.5,1197.69 ; v1(2725,1270) 2725.25,1269.75 2725.25,1197.94 R110.1@2725.5,1197.69 ; R110.1@2725.5,1191.69 2720.5,1196.69 R110.1@2721.5,1197.69 ; C107.1@2870.5,1106.69 2870.5,1141.69 2850.5,1161.69 2795.5,1161.69 2759.5,1197.69 R110.1@2725.5,1197.69 ; C107.1@2871.5,1111.69 2873.5,1109.69 R106.2@2873.5,1048.69 ; R106.2@2875.5,1041.69 2873.5,1043.69 R106.2@2873.5,1048.69 ; R106.2@2877.5,1044.69 R106.2@2873.5,1048.69 ; R110.1@2721.5,1197.69 R110.1@2725.5,1197.69
  other v1: 4955,1150 5005,1150 5055,1150 5105,1150 5155,1150 4955,1200 5005,1200 5055,1200 5105,1200 5155,1200 4955,1250 5005,1250 5055,1250 5105,1250 5155,1250 5025,1430 5075,1430 5125,1430 5025,1480 5075,1480 5125,1480 5025,1530 5075,1530 5125,1530 3470,1540.39 3520,1540.39 3570,1540.39 3620,1540.39 5025,1580 5075,1580 5125,1580 3470,1590.39 3520,1590.39 3570,1590.39 3620,1590.39 5025,1630 5075,1630 5125,1630 3765.39,1705.56 3815.39,1705.56 3954.6,1705.56 4004.6,1705.56 4220.39,1705.56 4270.39,1705.56 4409.6,1705.56 4459.6,1705.56 4675.39,1705.56 4725.39,1705.56 4914.6,1705.56 3470,1730.39 3520,1730.39 3570,1730.39 3620,1730.39 3765.39,1755.56 3815.39,1755.56 3954.6,1755.56 4004.6,1755.56 4220.39,1755.56 4270.39,1755.56 4409.6,1755.56 4459.6,1755.56 4675.39,1755.56 4725.39,1755.56 4864.6,1755.56 4914.6,1755.56 3470,1799.05 3520,1799.05 3570,1799.05 3620,1799.05 3765.39,1805.56 3815.39,1805.56 3954.6,1805.56 4004.6,1805.56 4220.39,1805.56 4270.39,1805.56 4409.6,1805.56 4459.6,1805.56 4675.39,1805.56 4725.39,1805.56 4864.6,1805.56 4914.6,1805.56 3470,1939.05 3520,1939.05 3570,1939.05 3620,1939.05 3470,1989.05 3520,1989.05 3570,1989.05 3620,1989.05
  other v2: 4989.99,749.99 4932.58,761.41 5047.39,761.4 4883.91,793.93 5096.06,793.92 4989.99,824.99 4851.4,842.59 5128.58,842.58 4936.95,846.96 5043.03,846.95 4839.99,900.01 4914.99,900 5065,899.99 5140,899.98 4936.96,953.04 5043.04,953.03 4851.41,957.41 5128.58,957.39 4990,975 4883.93,1006.07 5096.07,1006.06 4932.59,1038.58 5047.4,1038.58 4990,1050
"13.5 V (RTN)": C105.2 C108.2 C112.2 D102.A IC100.3 IC200.1 R102.2 R103.2 R114.2 TP105.1 X101.1 | length 3399.1
  Top Layer w15: R102.2@4520,595 v1(4520,650)
  Mid-Layer 3 w15: v1(2474.5,897.48) 2476.76,899.74 2917.02,1340 4215,1340 4420.87,1134.12 4420.87,749.12 v1(4520,650)
  Bottom Layer w15: IC100.3@2339.5,1091.69 2339.5,1055.5 2382.47,1012.52 2382.47,979.71 R114.2@2390.5,971.69 ; IC200.1@2340.5,847.4 2341.07,847.97 2370.78,847.97 C108.2@2420.5,897.69 ; IC100.3@2340.5,1091.69 2340.5,1131.69 2405.5,1196.69 C112.2@2499.5,1196.69 ; R114.2@2389.5,971.69 2389.5,934.19 2422,901.69 C108.2@2430.5,901.69
  Bottom Layer w30: C108.2@2430.5,897.69 2472.73,897.69 2472.95,897.48 v1(2474.5,897.48)
  other v1: 4395,-75 5175,-75 4475,315 4525,315 4575,315 4475,365 4525,365 4575,365 4475,415 4525,415 4575,415 4475,465 4525,465 4575,465 4475,515 4525,515 4575,515
  other v2: 4989.99,-5.01 4932.58,6.41 5047.39,6.4 4883.91,38.93 5096.06,38.92 4989.99,69.99 4851.4,87.59 5128.58,87.58 4936.95,91.96 5043.03,91.95 4839.99,145.01 4914.99,145 5065,144.99 5140,144.98 4936.96,198.04 5043.04,198.03 4851.41,202.41 5128.58,202.39 4990,220 4883.93,251.07 5096.07,251.06 4932.59,283.58 5047.4,283.58 4990,295
BIAS: C208.1 C209.1 D203.K R212.1 | length 1292.1
  Top Layer w20: D203.K@1305.39,960 1305.39,888 1313.39,880 C209.1@1420,880 v1(1490,880)
  Mid-Layer 2 w20: v1(1490,880) 1405,880 1370,845 1370,340 1420,290 1630,290 v1(1670,330)
  Bottom Layer w20: R212.1@1669,385 1669.5,384.5 1669.5,330.5 v1(1670,330)
"BIAS Winding": D203.A T200.5 | length 140.3
  Top Layer w35: D203.A@1444.21,960 1444.41,959.8 1584.11,959.8 T200.5@1584.3,959.6
"HV RTN": C207.2 C208.2 C209.2 C210.2 IC200.13 IC200.16-19 L200.4 R205.2 T200.6 TP202.1 TP203.1 | length 1198.6
  Top Layer w20: C208.2@1315,770 C209.2@1420,770 ; v1(1420,820) C209.2@1420,770 ; T200.6@1584.3,750.94 1573.25,762 1428,762 C209.2@1420,770
  Mid-Layer 2 w20: v1(1420,820) 1420,365 1445,340 1600,340 1625,365 1625,485 v1(1675,535)
  other v1: 1475,380 1525,380 1575,380 1845,385 1475,430 1525,430 1575,430 1845,435 760,450 810,450 860,450 910,450 1085,450 1135,450 1185,450 1235,450 1475,480 1525,480 1575,480 1475,530 1525,530 1475,580 1525,580 1575,580 1625,580 1675,580 1725,580 760,605 810,605 860,605 910,605 1085,605 1135,605 1185,605 1235,605 1475,630 1525,630 1575,630 1625,630 1675,630 1725,630 1775,630 1475,680 1525,680 1575,680 1625,680 1675,680 1725,680 1775,680 930,715 980,715 1030,715 1080,715
"HV+ (900 V)": C200.1 C202.1 L200.1 R200.1 R201.1 R202.2 T200.1 TP200.1
  other v1: 690,1455 740,1455 690,1505 740,1505 790,1505 690,1555 740,1555 790,1555 640,1605 690,1605 740,1605 790,1605 640,1655 690,1655 740,1655 790,1655 840,1655 640,1705 690,1705 740,1705 790,1705 840,1705 640,1755 690,1755 740,1755 690,1935 740,1935 690,1985 740,1985
IC200A_D: D200.A IC200.24 T200.3 TP201.1
  other v1: 1450,1370 1500,1370 1550,1370 1600,1370 1650,1370 1450,1420 1450,1470
NetC100_2: C100.2 R100.1 R101.1
  other v1: 4115,1080 4175,1080 4235,1080
NetC102_2: C102.2 C103.2 C104.2 C106.1 C108.1 C109.2 C110.2 D102.K IC200.2 Q100.S Q101.S R100.2 R101.2 R102.1 R103.1 R105.1 T200.9 T200.10 TP104.1 | length 373.2
  Bottom Layer w15: IC200.2@2340.5,817.87 2402.68,817.87 C108.1@2420.5,835.69
  Bottom Layer w30: C108.1@2430.5,835.69 C110.2@2540.27,835.69 ; v1(2545.5,546.69) 2545.5,507.33 C109.2@2548.14,504.69 ; 2606.5,840.69 C106.1@2665.5,840.69 ; C106.1@2666.5,840.69 R105.1@2740.5,840.69
  other v1: 4475,780 4525,780 4575,780 4475,830 4525,830 4575,830 2520,880 2560,880 2600,880 4475,880 4525,880 4575,880 4475,930 4525,930 4575,930 4475,980 4525,980 4575,980 3470,1238.26 3520,1238.26 3570,1238.26 3620,1238.26 3470,1381.73 3520,1381.73 3570,1381.73 3620,1381.73 3715.39,1384.3 3765.39,1384.3 3815.39,1384.3 3954.6,1384.3 4004.6,1384.3 4054.6,1384.3 4170.39,1384.3 4220.39,1384.3 4270.39,1384.3 4409.6,1384.3 4459.6,1384.3 4509.6,1384.3 4625.39,1384.3 4675.39,1384.3 4725.39,1384.3 4864.6,1384.3 3715.39,1429.3 3765.39,1429.3 3815.39,1429.3 3954.6,1429.3 4004.6,1429.3 4054.6,1429.3 4170.39,1429.3 4220.39,1429.3 4270.39,1429.3 4409.6,1429.3 4459.6,1429.3 4509.6,1429.3 4625.39,1429.3 4675.39,1429.3 4725.39,1429.3 4864.6,1429.3
NetC107_2: C107.2 R104.2 | length 78.7
  Bottom Layer w15: R104.2@2800.5,1036.69 2805,1041.19 2805,1107.19 C107.2@2809.5,1111.69
NetC109_1: C109.1 IC200.7 R109.2 | length 336.4
  Bottom Layer w15: IC200.7@2340.5,670.23 2341.07,669.66 2372.52,669.66 2427.5,614.69 C109.1@2548.14,614.69 2560.3,614.69 2566.09,608.9 2639.92,608.9 R109.2@2648.14,600.69
NetC110_1: C110.1 IC200.4 R115.1 | length 348.5
  Bottom Layer w15: IC200.4@2340.5,758.82 2418.37,758.82 2430.5,746.69 2467.49,746.69 2487.49,726.69 C110.1@2540.5,726.69 2541.34,725.84 2674.15,725.84 R115.1@2675,725
NetC113_1: C113.1 IC100.1 R112.2 | length 395.2
  Bottom Layer w12: IC100.1@2421.5,1128.69 IC100.1@2424.5,1125.69 ; C113.1@2486.5,1125.69 C113.1@2490.5,1121.69 ; C113.1@2495.5,1121.69 C113.1@2501,1121.69 ; C113.1@2500.5,1116.69 2506,1116.69 2530.99,1091.7 2600.49,1091.7 2610.5,1081.69 2610.5,1031.69 2595.5,1016.69 2521.23,1016.69 2514.5,1009.95 R112.2@2514.5,971.69
  Bottom Layer w15: IC100.1@2424.5,1125.69 C113.1@2486.5,1125.69
NetC113_2: C113.2 IC100.2 R113.2 R114.1 | length 257.6
  Bottom Layer w15: R114.1@2451.5,971.69 2421.5,1001.69 IC100.2@2421.5,1054.69 2423.5,1056.69 2424.5,1057.69 2496.5,1057.69 C113.2@2499.5,1060.69 ; C113.2@2495.5,1060.69 C113.2@2499.5,1060.69 ; R113.2@2575.5,1056.69 2571.5,1060.69 C113.2@2499.5,1060.69
NetC210_1: C210.1 IC200.14 R212.2 | length 273.6
  Bottom Layer w15: C210.1@1723.5,460.69 1765.69,460.69 1790.5,485.5 1790.5,541.69 1800.93,552.12 IC200.14@1839.5,552.12
  Bottom Layer w25: C210.1@1715.5,460.69 1723.5,460.69 1731,453.19 R212.2@1731,385
NetD100_A: D100.A R115.2 | length 125.6
  Bottom Layer w20: R115.2@2737,725 2832.41,725 2849.5,742.08 D100.A@2855.5,742.08
NetD100_K: D100.K D101.K | length 142.5
  Bottom Layer w15: D100.K@2855.5,871.3 2866,881.79 2885.6,881.79 2950.28,946.47 2950.28,950.13 2956.83,956.69 D101.K@2960.5,956.69
NetIC200_5: IC200.5 R107.2 R108.2 | length 2311.7
  Top Layer w15: R107.2@3725,1221 3725.5,1220.5 3789.5,1220.5 v1(3790,1220)
  Mid-Layer 3 w15: v1(2440.5,715.2) 2546.51,715.2 3106.31,1275 3920,1275 3935,1260 3935,1220 ; v1(3790,1220) 3935,1220 ; 3920,1220 3935,1235 3950,1220 ; v1(4055,1220) 3935,1220
  Bottom Layer w15: IC200.5@2340.5,729.29 2405.71,729.29 2419.37,715.62 2440.07,715.62 v1(2440.5,715.2) ; v1(4055,1220) 4055.5,1220.5 4114.5,1220.5 R108.2@4115,1221
NetL200_2: L200.2 R202.1 X200.1 X200.2
  other v1: -20,1420 30,1420 80,1420 130,1420 180,1420 230,1420 280,1420 330,1420 380,1420 -20,1470 30,1470 80,1470 130,1470 180,1470 230,1470 280,1470 330,1470 380,1470 -20,1520 30,1520 80,1520 130,1520 180,1520 230,1520 280,1520 330,1520 380,1520 -20,1570 30,1570 80,1570 130,1570 180,1570 230,1570 280,1570 330,1570 380,1570 -20,1620 30,1620 80,1620 130,1620 180,1620 230,1620 280,1620 330,1620 380,1620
